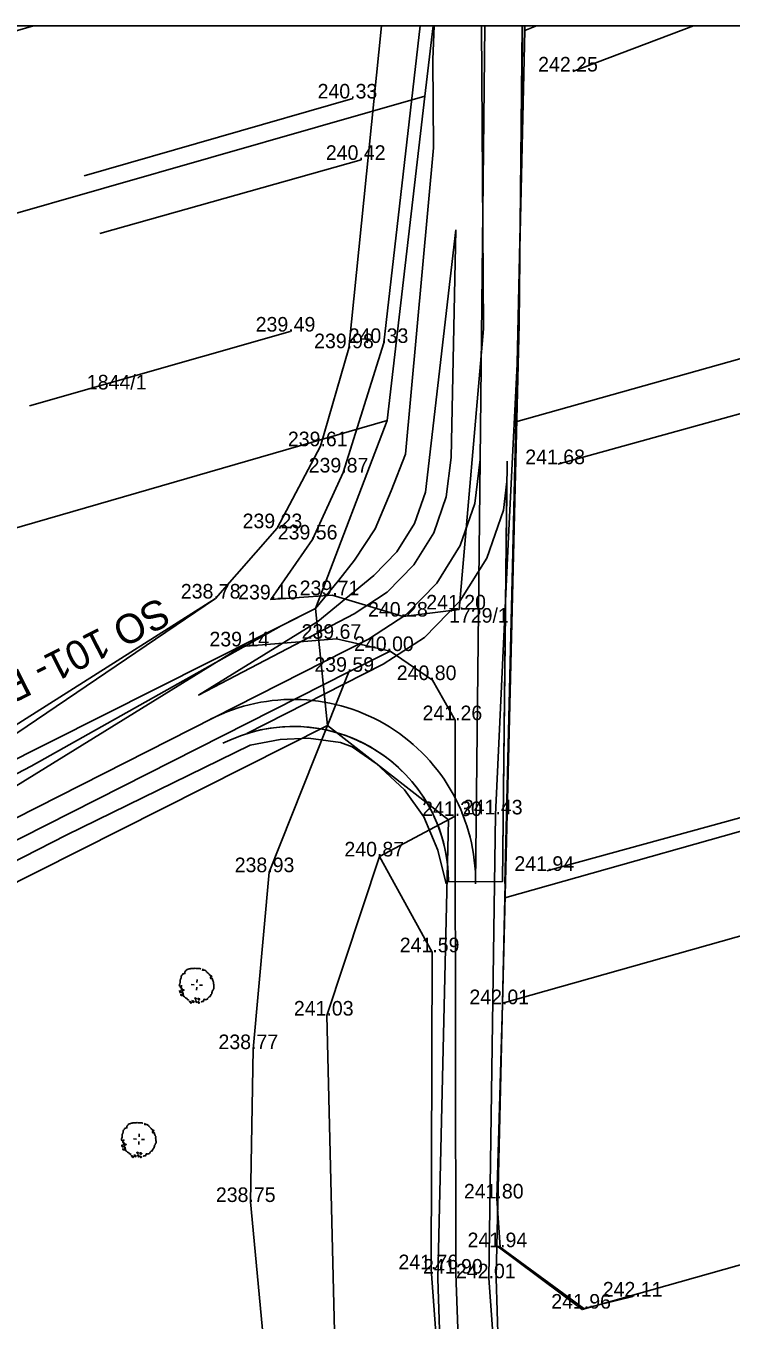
# Model space of a CAD drawing. Extents: x -601589 to -601440, y -1201842 to -1201527.
# Drawn here: x -601539.2 to -601490.8, y -1201615.4 to -1201526.7 of the extents above; entities that cross this region are included whole.
import ezdxf

# ---------------------------------------------------------------- set-up
doc = ezdxf.new("R2010")
doc.units = 0
for name, color, linetype in [('Definiční body', 7, 'Continuous'), ('Hranice parcel', 7, 'Continuous'), ('u_hrany', 7, 'Continuous'), ('u_osa', 7, 'Continuous'), ('u_popis', 7, 'Continuous'), ('u_rozšíření v obloucích', 7, 'Continuous'), ('u_terénní úpravy', 7, 'Continuous'), ('u_vysadba', 7, 'Continuous'), ('u_vyska', 7, 'Continuous'), ('x_rám', 7, 'Continuous')]:
    doc.layers.add(name, color=color, linetype=linetype)

msp = doc.modelspace()

# ---------------------------------------------------------------- linework, layer by layer
at = {"layer": 'Hranice parcel'}
for p, q in [((-601584.77, -1201539.96), (-601538.652, -1201526.653)), ((-601504.173, -1201526.653), (-601504.99, -1201526.96)), ((-601505.6, -1201553.8), (-601504.99, -1201526.96)), ((-601559.51, -1201545.16), (-601511.83, -1201531.46)), ((-601511.83, -1201531.46), (-601514.42, -1201553.71)), ((-601551.13, -1201564.33), (-601514.42, -1201553.71)), ((-601514.42, -1201553.71), (-601519.33, -1201566.6)), ((-601506.34, -1201586.43), (-601505.6, -1201553.8)), ((-601558.04, -1201586.08), (-601519.33, -1201566.6)), ((-601519.33, -1201566.6), (-601518.5, -1201574.62)), ((-601567.44, -1201599.25), (-601518.5, -1201574.62)), ((-601506.51, -1201593.65), (-601506.34, -1201586.43)), ((-601506.89, -1201610.28), (-601506.51, -1201593.65))]:
    msp.add_line(p, q, dxfattribs=at)
for points in [[(-601511.269, -1201526.653), (-601511.83, -1201531.46)], [(-601504.99, -1201526.96), (-601504.983, -1201526.653)], [(-601440.367, -1201534.711), (-601462.47, -1201541.67), (-601505.6, -1201553.8)], [(-601440.367, -1201567.784), (-601506.34, -1201586.43)], [(-601518.5, -1201574.62), (-601510.22, -1201581.07), (-601510.94, -1201612.53), (-601510.72, -1201619.53), (-601510.05, -1201624.75), (-601508.24, -1201633.75), (-601505.86, -1201640.82), (-601502.47, -1201648.58), (-601498.5, -1201656.04), (-601493.62, -1201663.46), (-601488.75, -1201670.45), (-601479.72, -1201682.69), (-601461.88, -1201705.09), (-601445.87, -1201723.83)], [(-601440.367, -1201574.955), (-601506.51, -1201593.65)], [(-601440.367, -1201590.59), (-601467.15, -1201605.07), (-601501.05, -1201614.65), (-601506.89, -1201610.28)], [(-601505.66, -1201626.3), (-601506.1, -1201624.1), (-601506.73, -1201619.21), (-601506.94, -1201612.51), (-601506.89, -1201610.28)]]:
    msp.add_lwpolyline(points, dxfattribs=at)
at = {"layer": 'u_hrany'}
for points in [[(-601517.05, -1201548.75), (-601514.794, -1201526.653)], [(-601512.157, -1201526.653), (-601514.64, -1201548.39)], [(-601509.48, -1201566.66), (-601507.81, -1201547.43), (-601507.939, -1201526.653)], [(-601505.167, -1201526.653), (-601505.37, -1201547.09), (-601506.1, -1201561.67), (-601507, -1201580.71), (-601507.44, -1201612.51), (-601506.59, -1201624.18), (-601504.84, -1201632.93)], [(-601501.69, -1201529.78), (-601493.43, -1201526.653)], [(-601516.77, -1201531.63), (-601535.18, -1201536.93)], [(-601516.2, -1201535.84), (-601534.1, -1201540.88)], [(-601506.52, -1201593.72), (-601505.37, -1201547.09)], [(-601521.05, -1201547.61), (-601538.91, -1201552.71)], [(-601517.05, -1201548.75), (-601518.98, -1201555.47), (-601521.95, -1201561.09), (-601526.18, -1201565.91), (-601543.22, -1201577.44), (-601564.63, -1201591.39), (-601571.15, -1201595.24), (-601583.39, -1201600.55), (-601588.867, -1201602.038)], [(-601509.48, -1201566.66), (-601513.31, -1201567.15), (-601518.19, -1201565.68), (-601522.39, -1201565.97), (-601519.52, -1201561.86), (-601517.42, -1201557.27), (-601514.64, -1201548.39)], [(-601502.71, -1201556.7), (-601478.63, -1201550.02)], [(-601583.7, -1201599.06), (-601568.87, -1201592.97), (-601526.18, -1201565.91)], [(-601588.867, -1201604.38), (-601581.97, -1201602.55), (-601570.67, -1201597.77), (-601563.01, -1201593.18), (-601542.69, -1201580.51), (-601524.37, -1201569.19), (-601517.89, -1201568.67), (-601514.2, -1201569.51), (-601511.31, -1201571.5), (-601509.75, -1201574.25)], [(-601514.2, -1201569.51), (-601517.03, -1201570.93), (-601522.49, -1201584.67), (-601523.6, -1201596.8), (-601523.78, -1201607.28), (-601522.35, -1201622.38), (-601520.26, -1201632.29), (-601514.11, -1201648.21), (-601507.05, -1201660.77), (-601502.96, -1201664.86), (-601510.13, -1201648.82), (-601514.08, -1201638.6), (-601517, -1201627.14), (-601517.98, -1201618.06), (-601518.55, -1201594.5), (-601514.93, -1201583.59), (-601509.76, -1201580.82)], [(-601570.67, -1201597.77), (-601544.7, -1201584.94), (-601517.03, -1201570.93)], [(-601503.47, -1201584.58), (-601461.71, -1201573.1)], [(-601507.17, -1201633.88), (-601509.44, -1201619.72), (-601509.7, -1201612.19), (-601509.76, -1201580.82), (-601509.75, -1201574.25)], [(-601514.93, -1201583.59), (-601511.33, -1201590.16), (-601511.4, -1201611.89), (-601510.42, -1201625.27), (-601508.49, -1201633.89)], [(-601500.93, -1201614.59), (-601506.68, -1201610.38), (-601506.9, -1201607.04), (-601506.52, -1201593.72)], [(-601497.57, -1201613.76), (-601500.93, -1201614.59)]]:
    msp.add_lwpolyline(points, dxfattribs=at)
at = {"layer": 'u_osa'}
msp.add_line((-601508.035, -1201556.382), (-601508.353, -1201585.463), dxfattribs=at)
msp.add_lwpolyline([(-601507.711, -1201526.653), (-601508.035, -1201556.382), (-601508.399, -1201559.4), (-601509.407, -1201562.268), (-601511.012, -1201564.849), (-601513.137, -1201567.023), (-601515.682, -1201568.685), (-601576.299, -1201599.446)], dxfattribs=at)
msp.add_arc((-601520.852, -1201585.326), 12.5, 359.37446, 116.90572, dxfattribs=at)
at = {"layer": 'u_rozšíření v obloucích'}
for p, q in [((-601506.187, -1201556.503), (-601506.501, -1201585.298)), ((-601506.501, -1201585.298), (-601510.207, -1201585.327))]:
    msp.add_line(p, q, dxfattribs=at)
for points in [[(-601509.714, -1201540.624), (-601511.779, -1201558.612), (-601512.537, -1201560.767), (-601513.743, -1201562.708), (-601515.334, -1201564.335), (-601519.165, -1201567.476), (-601527.336, -1201572.525)], [(-601509.714, -1201540.624), (-601511.779, -1201558.612), (-601512.537, -1201560.767), (-601513.743, -1201562.708), (-601515.334, -1201564.335), (-601519.165, -1201567.476), (-601527.336, -1201572.525), (-601516.684, -1201566.951), (-601514.414, -1201565.468), (-601512.595, -1201563.608), (-601511.221, -1201561.398), (-601510.359, -1201558.943), (-601510.034, -1201556.251), (-601509.714, -1201540.624)], [(-601510.207, -1201585.327), (-601506.501, -1201585.298), (-601506.202, -1201557.882), (-601506.44, -1201559.857), (-601507.593, -1201563.137), (-601509.429, -1201566.091), (-601511.86, -1201568.578), (-601514.679, -1201570.419), (-601524.039, -1201575.169)]]:
    msp.add_lwpolyline(points, dxfattribs=at)
for end in [116.90572, 107.41755]:
    msp.add_arc((-601520.852, -1201585.326), 10.646, 359.99466, end, dxfattribs=at)
at = {"layer": 'u_terénní úpravy'}
for points in [[(-601511.197, -1201526.653), (-601511.285, -1201528.955), (-601511.232, -1201535.024), (-601513.147, -1201556.002), (-601514.131, -1201558.519), (-601515.245, -1201561.131), (-601516.655, -1201563.291), (-601517.726, -1201564.657), (-601519.33, -1201566.6), (-601521.678, -1201567.781), (-601538.799, -1201577.408), (-601577.284, -1201597.587)], [(-601505.148, -1201526.653), (-601505.175, -1201535.09), (-601505.652, -1201556.084), (-601506.353, -1201585.447)], [(-601510.358, -1201585.479), (-601510.939, -1201583.156), (-601511.905, -1201580.866), (-601513.234, -1201579.022), (-601515.173, -1201577.212), (-601516.815, -1201576.086), (-601517.621, -1201575.775), (-601519.795, -1201575.475), (-601521.737, -1201575.568), (-601523.807, -1201575.966), (-601536.406, -1201582.122), (-601545.145, -1201586.599)]]:
    msp.add_lwpolyline(points, dxfattribs=at)
at = {"layer": 'u_vysadba'}
for points in [[(-601528.445, -1201591.696), (-601528.444, -1201591.667), (-601528.384, -1201591.641), (-601528.354, -1201591.628), (-601528.324, -1201591.615), (-601528.295, -1201591.616), (-601528.266, -1201591.618), (-601528.279, -1201591.588), (-601528.292, -1201591.558), (-601528.275, -1201591.515), (-601528.258, -1201591.472), (-601528.226, -1201591.43), (-601528.196, -1201591.402), (-601528.165, -1201591.374), (-601528.12, -1201591.347), (-601528.076, -1201591.35), (-601528.045, -1201591.322), (-601527.97, -1201591.297), (-601527.911, -1201591.285), (-601527.867, -1201591.273), (-601527.808, -1201591.276), (-601527.764, -1201591.264), (-601527.72, -1201591.266), (-601527.647, -1201591.27), (-601527.573, -1201591.259), (-601527.5, -1201591.263), (-601527.412, -1201591.268), (-601527.325, -1201591.272), (-601527.252, -1201591.276), (-601527.209, -1201591.293), (-601527.18, -1201591.309)], [(-601527.034, -1201591.302), (-601527.05, -1201591.331), (-601527.051, -1201591.36), (-601527.067, -1201591.388), (-601527.023, -1201591.376), (-601526.994, -1201591.378), (-601526.964, -1201591.379), (-601526.921, -1201591.396), (-601526.878, -1201591.398), (-601526.835, -1201591.43), (-601526.808, -1201591.461), (-601526.781, -1201591.506), (-601526.739, -1201591.538), (-601526.682, -1201591.584), (-601526.641, -1201591.631), (-601526.613, -1201591.661), (-601526.573, -1201591.722), (-601526.516, -1201591.754), (-601526.473, -1201591.786), (-601526.43, -1201591.803), (-601526.432, -1201591.832)], [(-601528.445, -1201591.696), (-601528.446, -1201591.711), (-601528.492, -1201591.752), (-601528.523, -1201591.78), (-601528.525, -1201591.824), (-601528.528, -1201591.868), (-601528.531, -1201591.926), (-601528.548, -1201591.969), (-601528.564, -1201591.998), (-601528.58, -1201592.026), (-601528.598, -1201592.084), (-601528.599, -1201592.113), (-601528.602, -1201592.171), (-601528.605, -1201592.215), (-601528.606, -1201592.244), (-601528.625, -1201592.316), (-601528.642, -1201592.36), (-601528.644, -1201592.403), (-601528.66, -1201592.432), (-601528.647, -1201592.462), (-601528.604, -1201592.479), (-601528.515, -1201592.454), (-601528.485, -1201592.441), (-601528.517, -1201592.498), (-601528.548, -1201592.526), (-601528.564, -1201592.554), (-601528.566, -1201592.598), (-601528.537, -1201592.599), (-601528.493, -1201592.602), (-601528.48, -1201592.632), (-601528.497, -1201592.675), (-601528.513, -1201592.703), (-601528.516, -1201592.747), (-601528.518, -1201592.791)], [(-601527.63, -1201592.389), (-601527.834, -1201592.378)], [(-601527.462, -1201592.544), (-601527.473, -1201592.749)], [(-601527.446, -1201592.238), (-601527.435, -1201592.033)], [(-601527.279, -1201592.408), (-601527.074, -1201592.404)], [(-601526.432, -1201591.832), (-601526.477, -1201591.844), (-601526.521, -1201591.857), (-601526.537, -1201591.885), (-601526.524, -1201591.915), (-601526.497, -1201591.96), (-601526.467, -1201591.947), (-601526.423, -1201591.935), (-601526.395, -1201591.966), (-601526.382, -1201591.996), (-601526.384, -1201592.025), (-601526.357, -1201592.085), (-601526.345, -1201592.129), (-601526.333, -1201592.174), (-601526.306, -1201592.219), (-601526.308, -1201592.249), (-601526.31, -1201592.292), (-601526.311, -1201592.322), (-601526.299, -1201592.366), (-601526.288, -1201592.425), (-601526.291, -1201592.484), (-601526.279, -1201592.543), (-601526.281, -1201592.572), (-601526.282, -1201592.601), (-601526.285, -1201592.645), (-601526.315, -1201592.673), (-601526.317, -1201592.702), (-601526.334, -1201592.745), (-601526.35, -1201592.773), (-601526.396, -1201592.815), (-601526.399, -1201592.873), (-601526.417, -1201592.931), (-601526.435, -1201593.003), (-601526.482, -1201593.059), (-601526.515, -1201593.131), (-601526.548, -1201593.188), (-601526.607, -1201593.214), (-601526.638, -1201593.241), (-601526.684, -1201593.283), (-601526.716, -1201593.325), (-601526.733, -1201593.368), (-601526.793, -1201593.394), (-601526.837, -1201593.407), (-601526.867, -1201593.42), (-601526.91, -1201593.403), (-601526.953, -1201593.386), (-601526.97, -1201593.429), (-601526.988, -1201593.487), (-601527.005, -1201593.53), (-601527.049, -1201593.542), (-601527.093, -1201593.54)], [(-601528.649, -1201592.784), (-601528.636, -1201592.814), (-601528.624, -1201592.858), (-601528.611, -1201592.888), (-601528.612, -1201592.917), (-601528.584, -1201592.934), (-601528.553, -1201592.906), (-601528.507, -1201592.864), (-601528.536, -1201592.863), (-601528.579, -1201592.831), (-601528.622, -1201592.814)], [(-601528.559, -1201593.023), (-601528.55, -1201593.111), (-601528.506, -1201593.113), (-601528.476, -1201593.115), (-601528.432, -1201593.103), (-601528.49, -1201593.085), (-601528.533, -1201593.083), (-601528.546, -1201593.053)], [(-601528.492, -1201592.851), (-601528.45, -1201592.897), (-601528.409, -1201592.943), (-601528.367, -1201592.974)], [(-601528.367, -1201592.974), (-601528.396, -1201592.973), (-601528.425, -1201592.971), (-601528.454, -1201592.97), (-601528.467, -1201592.94), (-601528.466, -1201592.911), (-601528.479, -1201592.881)], [(-601528.467, -1201592.662), (-601528.469, -1201592.705), (-601528.456, -1201592.735), (-601528.444, -1201592.78), (-601528.431, -1201592.81), (-601528.402, -1201592.811), (-601528.386, -1201592.783), (-601528.326, -1201592.757), (-601528.369, -1201592.74), (-601528.397, -1201592.724), (-601528.454, -1201592.692)], [(-601527.995, -1201593.433), (-601528.038, -1201593.416), (-601528.067, -1201593.4), (-601528.096, -1201593.399), (-601528.123, -1201593.353), (-601528.151, -1201593.337), (-601528.194, -1201593.306), (-601528.237, -1201593.289), (-601528.278, -1201593.243), (-601528.306, -1201593.212), (-601528.377, -1201593.179), (-601528.375, -1201593.135), (-601528.373, -1201593.091), (-601528.386, -1201593.061), (-601528.414, -1201593.045), (-601528.383, -1201593.003), (-601528.354, -1201593.004)], [(-601527.762, -1201593.446), (-601527.766, -1201593.519), (-601527.753, -1201593.563), (-601527.726, -1201593.594), (-601527.667, -1201593.582), (-601527.636, -1201593.555), (-601527.649, -1201593.525), (-601527.692, -1201593.508), (-601527.735, -1201593.491)], [(-601527.591, -1201593.264), (-601527.58, -1201593.338), (-601527.554, -1201593.383), (-601527.509, -1201593.371), (-601527.507, -1201593.342), (-601527.506, -1201593.313), (-601527.549, -1201593.296), (-601527.577, -1201593.28)], [(-601527.557, -1201593.442), (-601527.473, -1201593.519), (-601527.444, -1201593.536), (-601527.431, -1201593.566), (-601527.462, -1201593.593), (-601527.491, -1201593.592), (-601527.504, -1201593.562), (-601527.531, -1201593.516), (-601527.559, -1201593.486)], [(-601527.388, -1201593.304), (-601527.362, -1201593.364), (-601527.35, -1201593.409), (-601527.322, -1201593.44), (-601527.292, -1201593.427), (-601527.261, -1201593.384), (-601527.259, -1201593.355), (-601527.303, -1201593.353), (-601527.331, -1201593.337), (-601527.36, -1201593.32), (-601527.389, -1201593.319)], [(-601527.984, -1201593.492), (-601527.888, -1201593.615), (-601527.861, -1201593.66), (-601527.829, -1201593.618), (-601527.828, -1201593.589), (-601527.856, -1201593.572), (-601527.899, -1201593.555), (-601527.928, -1201593.539), (-601527.956, -1201593.523)], [(-601527.358, -1201593.555), (-601527.347, -1201593.629), (-601527.334, -1201593.659), (-601527.304, -1201593.646), (-601527.272, -1201593.603), (-601527.3, -1201593.573), (-601527.328, -1201593.556), (-601527.358, -1201593.555)], [(-601527.093, -1201593.54), (-601527.138, -1201593.552), (-601527.169, -1201593.579)], [(-601532.412, -1201602.277), (-601532.413, -1201602.292), (-601532.459, -1201602.333), (-601532.489, -1201602.361), (-601532.492, -1201602.405), (-601532.494, -1201602.449), (-601532.497, -1201602.507), (-601532.514, -1201602.55), (-601532.53, -1201602.578), (-601532.546, -1201602.607), (-601532.564, -1201602.664), (-601532.566, -1201602.694), (-601532.569, -1201602.752), (-601532.571, -1201602.796), (-601532.573, -1201602.825), (-601532.591, -1201602.897), (-601532.608, -1201602.94), (-601532.61, -1201602.984), (-601532.626, -1201603.013), (-601532.613, -1201603.043), (-601532.57, -1201603.059), (-601532.481, -1201603.035), (-601532.451, -1201603.022), (-601532.483, -1201603.079), (-601532.514, -1201603.106), (-601532.53, -1201603.135), (-601532.533, -1201603.179), (-601532.503, -1201603.18), (-601532.46, -1201603.182), (-601532.447, -1201603.212), (-601532.464, -1201603.255), (-601532.48, -1201603.284), (-601532.482, -1201603.328), (-601532.484, -1201603.372)], [(-601532.412, -1201602.277), (-601532.41, -1201602.248), (-601532.35, -1201602.222), (-601532.32, -1201602.209), (-601532.29, -1201602.196), (-601532.261, -1201602.197), (-601532.232, -1201602.199), (-601532.245, -1201602.169), (-601532.258, -1201602.139), (-601532.241, -1201602.096), (-601532.224, -1201602.053), (-601532.193, -1201602.011), (-601532.162, -1201601.983), (-601532.131, -1201601.955), (-601532.086, -1201601.928), (-601532.042, -1201601.931), (-601532.011, -1201601.903), (-601531.937, -1201601.878), (-601531.878, -1201601.866), (-601531.833, -1201601.854), (-601531.775, -1201601.857), (-601531.73, -1201601.845), (-601531.686, -1201601.847), (-601531.613, -1201601.851), (-601531.539, -1201601.84), (-601531.466, -1201601.844), (-601531.379, -1201601.849), (-601531.291, -1201601.853), (-601531.218, -1201601.857), (-601531.175, -1201601.874), (-601531.147, -1201601.89)], [(-601531, -1201601.883), (-601531.016, -1201601.912), (-601531.018, -1201601.941), (-601531.034, -1201601.969), (-601530.989, -1201601.957), (-601530.96, -1201601.958), (-601530.931, -1201601.96), (-601530.888, -1201601.977), (-601530.844, -1201601.979), (-601530.802, -1201602.011), (-601530.774, -1201602.042), (-601530.747, -1201602.087), (-601530.705, -1201602.118), (-601530.649, -1201602.165), (-601530.607, -1201602.211), (-601530.58, -1201602.242), (-601530.539, -1201602.303), (-601530.482, -1201602.335), (-601530.44, -1201602.367), (-601530.397, -1201602.384), (-601530.398, -1201602.413)], [(-601531.596, -1201602.97), (-601531.8, -1201602.959)], [(-601531.429, -1201603.125), (-601531.439, -1201603.33)], [(-601531.412, -1201602.819), (-601531.402, -1201602.614)], [(-601531.246, -1201602.989), (-601531.04, -1201602.985)], [(-601530.398, -1201602.413), (-601530.443, -1201602.425), (-601530.487, -1201602.437), (-601530.504, -1201602.466), (-601530.491, -1201602.496), (-601530.464, -1201602.541), (-601530.434, -1201602.528), (-601530.389, -1201602.516), (-601530.361, -1201602.547), (-601530.348, -1201602.577), (-601530.35, -1201602.606), (-601530.324, -1201602.666), (-601530.312, -1201602.71), (-601530.299, -1201602.755), (-601530.272, -1201602.8), (-601530.274, -1201602.829), (-601530.276, -1201602.873), (-601530.278, -1201602.902), (-601530.265, -1201602.947), (-601530.254, -1201603.006), (-601530.257, -1201603.065), (-601530.246, -1201603.124), (-601530.247, -1201603.153), (-601530.249, -1201603.182), (-601530.251, -1201603.226), (-601530.282, -1201603.254), (-601530.283, -1201603.283), (-601530.3, -1201603.326), (-601530.316, -1201603.354), (-601530.362, -1201603.396), (-601530.365, -1201603.454), (-601530.383, -1201603.512), (-601530.402, -1201603.584), (-601530.449, -1201603.64), (-601530.482, -1201603.712), (-601530.514, -1201603.768), (-601530.574, -1201603.795), (-601530.605, -1201603.822), (-601530.651, -1201603.864), (-601530.682, -1201603.906), (-601530.699, -1201603.949), (-601530.759, -1201603.975), (-601530.804, -1201603.987), (-601530.834, -1201604.001), (-601530.877, -1201603.984), (-601530.92, -1201603.967), (-601530.937, -1201604.01), (-601530.954, -1201604.067), (-601530.971, -1201604.11), (-601531.016, -1201604.123), (-601531.06, -1201604.12)], [(-601532.616, -1201603.365), (-601532.603, -1201603.395), (-601532.59, -1201603.439), (-601532.577, -1201603.469), (-601532.579, -1201603.498), (-601532.55, -1201603.514), (-601532.52, -1201603.487), (-601532.474, -1201603.445), (-601532.503, -1201603.444), (-601532.545, -1201603.412), (-601532.588, -1201603.395)], [(-601532.526, -1201603.604), (-601532.516, -1201603.692), (-601532.472, -1201603.694), (-601532.443, -1201603.696), (-601532.398, -1201603.684), (-601532.456, -1201603.666), (-601532.5, -1201603.664), (-601532.513, -1201603.634)], [(-601532.458, -1201603.431), (-601532.417, -1201603.478), (-601532.375, -1201603.524), (-601532.333, -1201603.555)], [(-601532.333, -1201603.555), (-601532.362, -1201603.554), (-601532.391, -1201603.552), (-601532.421, -1201603.551), (-601532.434, -1201603.521), (-601532.432, -1201603.491), (-601532.445, -1201603.461)], [(-601532.434, -1201603.242), (-601532.436, -1201603.286), (-601532.423, -1201603.316), (-601532.411, -1201603.361), (-601532.397, -1201603.391), (-601532.368, -1201603.392), (-601532.352, -1201603.364), (-601532.292, -1201603.338), (-601532.335, -1201603.321), (-601532.364, -1201603.305), (-601532.42, -1201603.272)], [(-601531.962, -1201604.014), (-601532.005, -1201603.997), (-601532.033, -1201603.981), (-601532.062, -1201603.98), (-601532.089, -1201603.934), (-601532.118, -1201603.918), (-601532.16, -1201603.886), (-601532.203, -1201603.87), (-601532.245, -1201603.823), (-601532.272, -1201603.793), (-601532.344, -1201603.76), (-601532.341, -1201603.716), (-601532.339, -1201603.672), (-601532.352, -1201603.642), (-601532.381, -1201603.626), (-601532.349, -1201603.584), (-601532.32, -1201603.585)], [(-601531.95, -1201604.073), (-601531.854, -1201604.196), (-601531.827, -1201604.241), (-601531.796, -1201604.199), (-601531.794, -1201604.169), (-601531.823, -1201604.153), (-601531.866, -1201604.136), (-601531.894, -1201604.12), (-601531.923, -1201604.104)], [(-601531.728, -1201604.026), (-601531.732, -1201604.099), (-601531.72, -1201604.144), (-601531.692, -1201604.175), (-601531.633, -1201604.163), (-601531.602, -1201604.136), (-601531.615, -1201604.106), (-601531.658, -1201604.089), (-601531.701, -1201604.072)], [(-601531.558, -1201603.845), (-601531.547, -1201603.919), (-601531.52, -1201603.964), (-601531.475, -1201603.952), (-601531.474, -1201603.923), (-601531.472, -1201603.894), (-601531.515, -1201603.877), (-601531.544, -1201603.86)], [(-601531.523, -1201604.023), (-601531.439, -1201604.1), (-601531.411, -1201604.116), (-601531.398, -1201604.146), (-601531.428, -1201604.174), (-601531.458, -1201604.173), (-601531.471, -1201604.143), (-601531.498, -1201604.097), (-601531.525, -1201604.066)], [(-601531.355, -1201603.885), (-601531.329, -1201603.945), (-601531.316, -1201603.99), (-601531.289, -1201604.02), (-601531.259, -1201604.007), (-601531.227, -1201603.965), (-601531.226, -1201603.936), (-601531.269, -1201603.934), (-601531.298, -1201603.917), (-601531.326, -1201603.901), (-601531.355, -1201603.9)], [(-601531.324, -1201604.136), (-601531.313, -1201604.209), (-601531.3, -1201604.239), (-601531.27, -1201604.226), (-601531.239, -1201604.184), (-601531.266, -1201604.153), (-601531.295, -1201604.137), (-601531.324, -1201604.136)], [(-601531.06, -1201604.12), (-601531.104, -1201604.133), (-601531.135, -1201604.16)]]:
    msp.add_lwpolyline(points, dxfattribs=at)
at = {"layer": 'x_rám'}
msp.add_lwpolyline([(-601440.367, -1201526.653), (-601440.367, -1201841.653), (-601588.867, -1201841.653), (-601588.867, -1201526.653)], close=True, dxfattribs=at)

# ---------------------------------------------------------------- texts
at = {"layer": 'Definiční body'}
for s, p in [('1844/1', (-601534.99, -1201551.576)), ('1729/1', (-601510.17, -1201567.566))]:
    msp.add_text(s, height=1, dxfattribs=at).set_placement(p)
at = {"layer": 'u_popis'}
msp.add_text('SO 101- Polní cesta C2', height=2, rotation=206.90572, dxfattribs=at).set_placement((-601529.971, -1201565.781))
at = {"layer": 'u_vyska'}
for s, p in [('242.25', (-601504.064, -1201529.78)), ('240.33', (-601519.179, -1201531.63)), ('240.42', (-601518.613, -1201535.84)), ('239.49', (-601523.422, -1201547.61)), ('239.98', (-601519.418, -1201548.75)), ('240.33', (-601517.049, -1201548.39)), ('239.61', (-601521.215, -1201555.47)), ('241.68', (-601504.948, -1201556.7)), ('239.87', (-601519.79, -1201557.27)), ('239.23', (-601524.319, -1201561.09)), ('239.56', (-601521.907, -1201561.86)), ('238.78', (-601528.55, -1201565.91)), ('239.16', (-601524.622, -1201565.97)), ('239.71', (-601520.407, -1201565.68)), ('241.20', (-601511.734, -1201566.66)), ('240.28', (-601515.719, -1201567.15)), ('239.67', (-601520.278, -1201568.67)), ('239.14', (-601526.589, -1201569.19)), ('240.00', (-601516.679, -1201569.51)), ('239.59', (-601519.398, -1201570.93)), ('240.80', (-601513.753, -1201571.5)), ('241.26', (-601511.988, -1201574.25)), ('241.30', (-601512.014, -1201580.82)), ('241.43', (-601509.224, -1201580.71)), ('240.87', (-601517.34, -1201583.59)), ('238.93', (-601524.859, -1201584.67)), ('241.94', (-601505.693, -1201584.58)), ('241.59', (-601513.549, -1201590.16)), ('242.01', (-601508.776, -1201593.72)), ('241.03', (-601520.804, -1201594.5)), ('238.77', (-601525.971, -1201596.8)), ('238.75', (-601526.15, -1201607.28)), ('241.80', (-601509.154, -1201607.04)), ('241.94', (-601508.903, -1201610.38)), ('241.76', (-601513.638, -1201611.89)), ('241.90', (-601511.953, -1201612.19)), ('242.01', (-601509.696, -1201612.51)), ('242.11', (-601499.637, -1201613.76)), ('241.96', (-601503.166, -1201614.59))]:
    msp.add_text(s, height=1, dxfattribs=at).set_placement(p)

doc.saveas('drawing.dxf')
